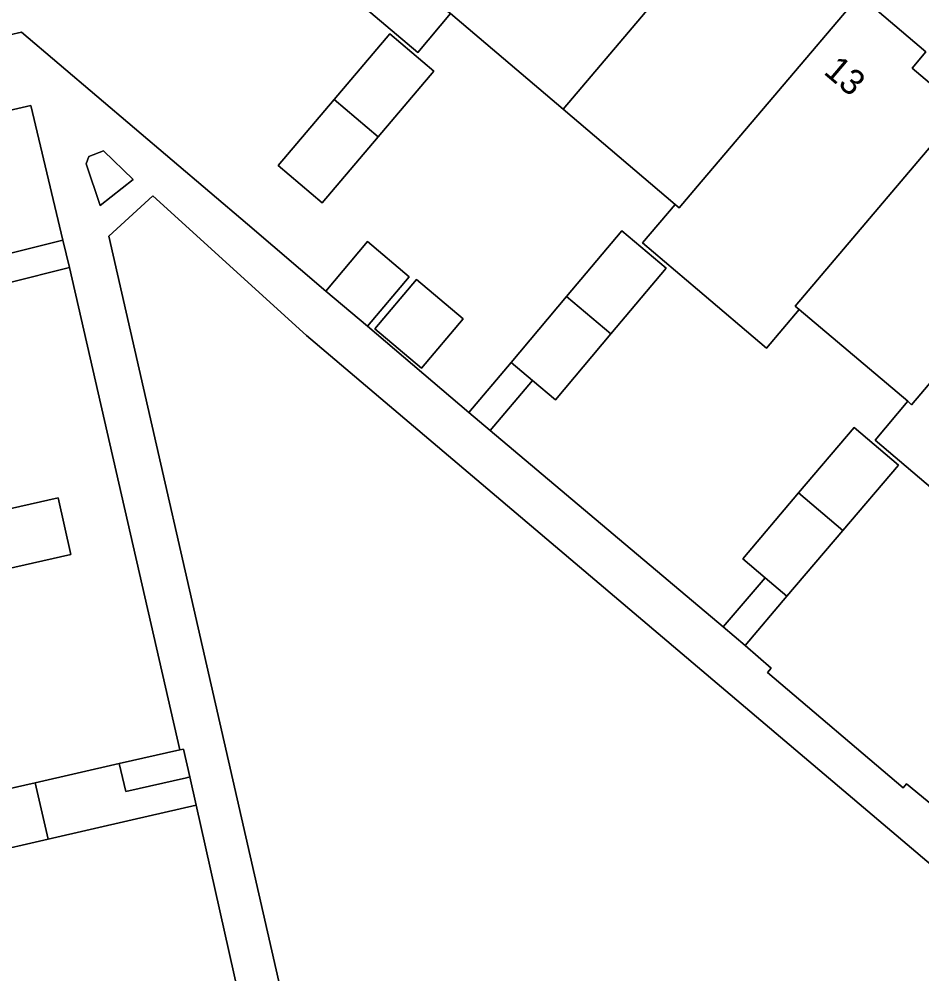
# Model space of a CAD drawing. Extents: x 156412 to 157779, y 382335 to 383768.
# Drawn here: x 156973.27 to 157008.84, y 382800.53 to 382838.16 of the extents above; entities that cross this region are included whole.
import ezdxf

# ---------------------------------------------------------------- set-up
doc = ezdxf.new("R2010")
doc.units = 0
for name, color, linetype in [('IMGEO_Erf', 7, 'Continuous'), ('IMGEO_Pand', 7, 'Continuous'), ('IMGEO_Pand_nummerreeks', 7, 'Continuous'), ('IMGEO_Voetpad_open', 7, 'Continuous')]:
    doc.layers.add(name, color=color, linetype=linetype)

msp = doc.modelspace()

# ---------------------------------------------------------------- linework, layer by layer
at = {"layer": 'IMGEO_Erf'}
for points in [[(157011.713, 382817.561), (157006.989, 382821.57), (157008.283, 382823.095), (157004.004, 382826.72), (157002.709, 382825.196), (157000, 382827.497), (156997.834, 382829.337), (156999.12, 382830.85), (156994.703, 382834.611), (156990.265, 382838.372), (156988.973, 382836.846), (156984.103, 382840.969), (156985.39, 382842.489), (156981.86, 382845.483), (156978.289, 382841.269), (156976.092, 382838.674), (156974.35, 382840.15), (156976.547, 382842.745), (156978.826, 382845.436), (156974.937, 382848.74), (156976.048, 382850.048), (156969.215, 382848.468)], [(157006.377, 382839.1), (157008.997, 382836.873), (157008.447, 382836.225), (157010.236, 382834.712)], [(156971.976, 382837.32), (156973.36, 382837.639), (156982.269, 382830.081), (156985.349, 382827.439), (156986.989, 382829.388), (156988.633, 382828.004), (156986.992, 382826.056), (156990.989, 382822.653), (156992.65, 382824.626), (156994.84, 382827.227), (156997.02, 382829.816), (156998.767, 382828.345), (156996.587, 382825.756), (156994.397, 382823.155), (156993.492, 382823.917), (156991.831, 382821.944), (156996.666, 382817.867), (157001.01, 382814.21), (157002.655, 382816.146), (157001.777, 382816.893), (157003.979, 382819.484), (157006.17, 382822.062), (157007.908, 382820.584), (157005.717, 382818.006), (157003.515, 382815.415), (157001.87, 382813.479), (157002.901, 382812.578), (157002.754, 382812.405), (157008.103, 382807.867), (157008.233, 382808.02), (157009.262, 382807.175)]]:
    msp.add_lwpolyline(points, dxfattribs=at)
for points in [[(156985.213, 382830.92), (156983.478, 382832.393), (156985.678, 382834.986), (156987.871, 382837.571), (156989.607, 382836.099), (156987.413, 382833.513)], [(156975.253, 382828.372), (156972.848, 382827.769), (156969.55, 382826.943), (156966.282, 382826.125), (156965.728, 382828.341), (156968.995, 382829.159), (156972.293, 382829.985), (156972.58, 382828.838), (156974.986, 382829.441), (156973.725, 382834.757), (156962.651, 382832.195), (156963.867, 382826.94), (156965.816, 382827.389), (156967.03, 382822.118), (156967.118, 382821.736), (156965.169, 382821.287), (156966.297, 382816.406), (156967.512, 382811.145), (156971.383, 382812.039), (156972.382, 382807.717), (156973.898, 382808.065), (156977.212, 382808.826), (156979.606, 382809.361)], [(156976.459, 382830.808), (156977.758, 382831.84), (156976.595, 382832.967), (156976.017, 382832.745), (156975.905, 382832.456)], [(156978.54, 382831.194), (156976.806, 382829.603), (156986.917, 382785.266), (156989.794, 382772.985), (156990.047, 382772.657), (156990.34, 382772.645), (157000.04, 382784.357), (157014.027, 382800.749), (156984.584, 382825.687)], [(156988.92, 382827.898), (156990.762, 382826.347), (156989.127, 382824.405), (156987.285, 382825.956)], [(156968.688, 382815.571), (156968.186, 382817.804), (156971.486, 382818.545), (156974.803, 382819.29), (156975.304, 382817.056), (156971.987, 382816.311)], [(156980.247, 382807.178), (156977.724, 382806.599), (156974.41, 382805.838), (156971.893, 382805.26), (156972.812, 382801.286), (156972.048, 382801.109), (156973.04, 382796.781), (156976.343, 382797.537), (156979.657, 382798.296), (156982.11, 382798.858)]]:
    msp.add_lwpolyline(points, close=True, dxfattribs=at)
at = {"layer": 'IMGEO_Pand'}
for points in [[(156990.265, 382838.372), (156990.119, 382838.48), (156997.221, 382846.858), (156997.056, 382846.998), (156996.507, 382846.349), (156994.714, 382847.863), (156995.264, 382848.511), (156992.642, 382850.735), (156985.542, 382842.36), (156985.39, 382842.489), (156984.103, 382840.969), (156988.973, 382836.846)], [(156990.265, 382838.372), (156994.703, 382834.611), (157000, 382840.858), (157001.798, 382842.978), (157001.63, 382843.12), (157001.081, 382842.471), (157000, 382843.389), (156999.294, 382843.989), (156999.843, 382844.638), (156997.221, 382846.858), (156990.119, 382838.48)], [(157006.377, 382839.1), (157006.221, 382839.233), (157005.67, 382838.585), (157003.874, 382840.105), (157004.424, 382840.754), (157001.798, 382842.978), (157000, 382840.858), (156994.703, 382834.611), (156999.12, 382830.85), (156999.273, 382830.721), (157000, 382831.578)], [(157006.377, 382839.1), (157000, 382831.578), (156999.273, 382830.721), (156999.12, 382830.85), (156997.834, 382829.337), (157000, 382827.497), (157002.709, 382825.196), (157004.004, 382826.72), (157003.849, 382826.841), (157010.952, 382835.219), (157010.786, 382835.36), (157010.236, 382834.712), (157008.447, 382836.225), (157008.997, 382836.873)], [(156987.413, 382833.513), (156989.607, 382836.099), (156987.871, 382837.571), (156985.678, 382834.986)], [(157004.004, 382826.72), (157008.283, 382823.095), (157008.426, 382822.961), (157015.531, 382831.342), (157015.356, 382831.49), (157014.806, 382830.842), (157013.024, 382832.346), (157013.574, 382832.994), (157010.952, 382835.219), (157003.849, 382826.841)], [(156987.413, 382833.513), (156985.678, 382834.986), (156983.478, 382832.393), (156985.213, 382830.92)], [(157008.283, 382823.095), (157006.989, 382821.57), (157011.713, 382817.561), (157020.103, 382827.455), (157019.919, 382827.611), (157019.37, 382826.962), (157017.627, 382828.449), (157018.139, 382829.128), (157015.531, 382831.342), (157008.426, 382822.961)], [(156974.986, 382829.441), (156972.58, 382828.838), (156972.293, 382829.985), (156968.995, 382829.159), (156969.55, 382826.943), (156972.848, 382827.769), (156975.253, 382828.372)], [(156994.84, 382827.227), (156996.587, 382825.756), (156998.767, 382828.345), (156997.02, 382829.816)], [(156985.349, 382827.439), (156986.992, 382826.056), (156988.633, 382828.004), (156986.989, 382829.388)], [(156987.285, 382825.956), (156989.127, 382824.405), (156990.762, 382826.347), (156988.92, 382827.898)], [(156996.587, 382825.756), (156994.84, 382827.227), (156992.65, 382824.626), (156993.492, 382823.917), (156994.397, 382823.155)], [(156993.492, 382823.917), (156992.65, 382824.626), (156990.989, 382822.653), (156991.831, 382821.944)], [(157005.717, 382818.006), (157007.908, 382820.584), (157006.17, 382822.062), (157003.979, 382819.484)], [(156971.486, 382818.545), (156971.987, 382816.311), (156975.304, 382817.056), (156974.803, 382819.29)], [(157005.717, 382818.006), (157003.979, 382819.484), (157001.777, 382816.893), (157002.655, 382816.146), (157003.515, 382815.415)], [(157003.515, 382815.415), (157002.655, 382816.146), (157001.01, 382814.21), (157001.87, 382813.479)], [(156979.606, 382809.361), (156977.212, 382808.826), (156977.467, 382807.715), (156979.866, 382808.265), (156979.99, 382808.294), (156979.738, 382809.391)], [(156979.99, 382808.294), (156979.866, 382808.265), (156977.467, 382807.715), (156977.212, 382808.826), (156973.898, 382808.065), (156974.41, 382805.838), (156977.724, 382806.599), (156980.247, 382807.178)], [(156973.898, 382808.065), (156972.382, 382807.717), (156970.603, 382807.308), (156970.819, 382806.367), (156971.114, 382805.081), (156971.893, 382805.26), (156974.41, 382805.838)]]:
    msp.add_lwpolyline(points, close=True, dxfattribs=at)
at = {"layer": 'IMGEO_Voetpad_open'}
for points in [[(157009.262, 382807.175), (157008.233, 382808.02), (157008.103, 382807.867), (157002.754, 382812.405), (157002.901, 382812.578), (157001.87, 382813.479), (157001.01, 382814.21), (156996.666, 382817.867), (156991.831, 382821.944), (156990.989, 382822.653), (156986.992, 382826.056), (156985.349, 382827.439), (156982.269, 382830.081), (156973.36, 382837.639), (156971.976, 382837.32)], [(156962.651, 382832.195), (156973.725, 382834.757), (156974.986, 382829.441), (156975.253, 382828.372), (156979.606, 382809.361), (156979.738, 382809.391), (156979.99, 382808.294), (156980.247, 382807.178), (156982.11, 382798.858)]]:
    msp.add_lwpolyline(points, dxfattribs=at)
for points in [[(156976.459, 382830.808), (156975.905, 382832.456), (156976.017, 382832.745), (156976.595, 382832.967), (156977.758, 382831.84)], [(156990.34, 382772.645), (156990.047, 382772.657), (156989.794, 382772.985), (156986.917, 382785.266), (156976.806, 382829.603), (156978.54, 382831.194), (156984.584, 382825.687), (157014.027, 382800.749), (157000.04, 382784.357)]]:
    msp.add_lwpolyline(points, close=True, dxfattribs=at)

# ---------------------------------------------------------------- texts
at = {"layer": 'IMGEO_Pand_nummerreeks'}
msp.add_text('13', height=1, rotation=319.6318, dxfattribs=at).set_placement((157004.924, 382836.03))

doc.saveas('drawing.dxf')
